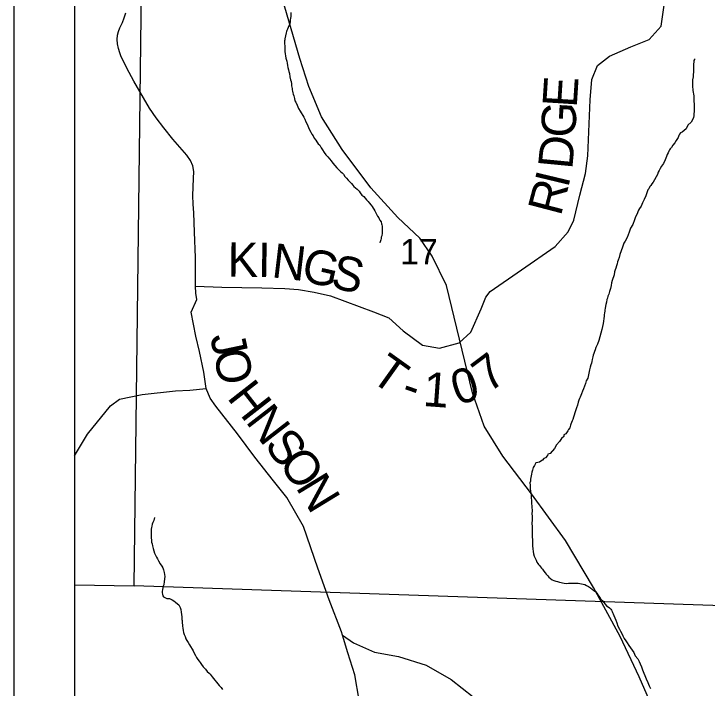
# Model space of a CAD drawing. Extents: x -14196 to 143, y -6096 to 28.
# Drawn here: x 58.003 to 59.148, y 19.711 to 20.825 of the extents above; entities that cross this region are included whole.
import ezdxf

# ---------------------------------------------------------------- set-up
doc = ezdxf.new("R2010")
doc.units = 0
for name, color, linetype in [('GM_X_Corporation', 7, 'Continuous'), ('GM_X_County_Road', 7, 'Continuous'), ('GM_X_County_Road_Text', 7, 'Continuous'), ('GM_X_Minor_River', 7, 'Continuous'), ('GM_X_Rail_Line', 7, 'Continuous'), ('GM_X_Section_Text', 7, 'Continuous'), ('GM_X_Township_Road', 7, 'Continuous'), ('GM_X_Township_Road_Text', 7, 'Continuous'), ('SH_Data', 7, 'Continuous')]:
    doc.layers.add(name, color=color, linetype=linetype)

msp = doc.modelspace()

# ---------------------------------------------------------------- linework, layer by layer
at = {"layer": 'GM_X_Corporation'}
for points in [[(64.9028, 18.7286), (64.9028, 23.6985), (58.1028, 23.6985), (58.1028, 18.8711)], [(62.1999, 18.7816), (62.2235, 19.866), (62.2323, 20.4208), (62.2487, 21.1358), (62.2751, 22.2884), (62.2815, 22.5484), (62.2824, 22.5866), (62.306, 23.4402), (61.9207, 23.4521), (60.7524, 23.485), (60.7179, 23.4857), (60.6994, 23.486), (60.6731, 23.4865), (60.4232, 23.4912), (60.4233, 23.5426), (60.4242, 23.5839), (60.4246, 23.6029), (60.4257, 23.6513), (60.4267, 23.6985), (58.1028, 23.6985), (58.1028, 18.8711)]]:
    msp.add_lwpolyline(points, dxfattribs=at)
for points in [[(58.1028, 20.874), (58.1028, 19.8822), (58.2013, 19.8806), (58.2134, 20.8668), (58.2133, 20.8703)], [(59.2185, 20.859), (59.2056, 19.8463), (58.2013, 19.8806), (58.2134, 20.8668)]]:
    msp.add_lwpolyline(points, close=True, dxfattribs=at)
at = {"layer": 'GM_X_County_Road'}
for points in [[(58.3029, 20.3753), (58.3027, 20.3824), (58.3027, 20.4227), (58.3014, 20.4645), (58.2999, 20.4966), (58.2989, 20.5108), (58.2985, 20.5254), (58.2995, 20.5532), (58.3002, 20.5649), (58.2983, 20.5742), (58.2946, 20.583), (58.2886, 20.5917), (58.2655, 20.6184), (58.2506, 20.6371), (58.2381, 20.6534), (58.2271, 20.6697), (58.2011, 20.714), (58.1931, 20.7284), (58.1882, 20.7376), (58.1842, 20.7458), (58.1803, 20.7541), (58.1776, 20.7611), (58.1755, 20.7679), (58.1739, 20.7758), (58.1734, 20.7828), (58.1738, 20.7898), (58.1755, 20.7959), (58.1781, 20.8022), (58.1825, 20.8111), (58.1851, 20.8185), (58.1878, 20.8268)], [(58.3206, 20.2064), (58.3165, 20.2333), (58.3092, 20.2673), (58.3033, 20.293), (58.2954, 20.3327), (58.3051, 20.3536), (58.3036, 20.3641), (58.3029, 20.3753)], [(58.5455, 19.7992), (58.5439, 19.8046), (58.5236, 19.8573), (58.5048, 19.9096), (58.481, 19.9782), (58.4536, 20.0262), (58.4316, 20.0537), (58.401, 20.0929), (58.3723, 20.1313), (58.3366, 20.1771), (58.3271, 20.1906), (58.3206, 20.2064)], [(58.5729, 19.6917), (58.5662, 19.7333), (58.5543, 19.7699), (58.5455, 19.7992)], [(58.5455, 19.7992), (58.5637, 19.7865), (58.5987, 19.771), (58.638, 19.764), (58.6835, 19.7496), (58.7251, 19.726), (58.7612, 19.6969)]]:
    msp.add_lwpolyline(points, dxfattribs=at)
at = {"layer": 'GM_X_Minor_River'}
for points in [[(58.4601, 20.8272), (58.4601, 20.8246), (58.4601, 20.8208), (58.4598, 20.8181), (58.4594, 20.8154), (58.4591, 20.8124), (58.4584, 20.809), (58.4569, 20.8055), (58.4558, 20.8025), (58.4547, 20.7998), (58.4539, 20.7979), (58.4532, 20.796), (58.4525, 20.7941), (58.4514, 20.7891), (58.4503, 20.7842), (58.4503, 20.7823), (58.45, 20.7804), (58.45, 20.7785), (58.45, 20.7751), (58.4501, 20.7728), (58.4501, 20.7701), (58.4501, 20.7682), (58.4501, 20.7659), (58.4506, 20.7633), (58.4518, 20.7519), (58.4538, 20.7473), (58.4542, 20.7436), (58.4546, 20.7398), (58.4554, 20.7367), (58.4562, 20.7329), (58.457, 20.7299), (58.4578, 20.7269), (58.4587, 20.7212), (58.4599, 20.7163), (58.461, 20.7136), (58.4611, 20.7098), (58.4615, 20.7064), (58.4619, 20.7041), (58.4623, 20.7022), (58.4627, 20.6996), (58.4631, 20.6977), (58.4635, 20.695), (58.4643, 20.6924), (58.4651, 20.6897), (58.4663, 20.6852), (58.4671, 20.6814), (58.4687, 20.6791), (58.4706, 20.6746), (58.473, 20.6689), (58.4757, 20.6644), (58.4815, 20.6545), (58.4834, 20.6511), (58.485, 20.647), (58.4873, 20.6428), (58.4893, 20.6375), (58.4912, 20.6337), (58.4932, 20.63), (58.4951, 20.6266), (58.4974, 20.6235), (58.499, 20.6201), (58.5013, 20.6167), (58.5032, 20.6137), (58.5056, 20.6103), (58.5079, 20.6081), (58.5102, 20.6039), (58.5125, 20.6005), (58.5152, 20.5964), (58.5183, 20.5926), (58.5214, 20.5888), (58.5241, 20.5858), (58.5268, 20.5824), (58.5299, 20.5787), (58.533, 20.5745), (58.5364, 20.5707), (58.5395, 20.5677), (58.5422, 20.5647), (58.5453, 20.5625), (58.5472, 20.5602), (58.5495, 20.5568), (58.5522, 20.5538), (58.5549, 20.5504), (58.558, 20.5474), (58.5603, 20.5448), (58.5626, 20.5421), (58.5645, 20.5399), (58.5668, 20.5376), (58.5699, 20.5354), (58.573, 20.5324)], [(59.1272, 20.7507), (59.1268, 20.7496), (59.1261, 20.7481), (59.1257, 20.7454), (59.1254, 20.7424), (59.1251, 20.7397), (59.1251, 20.737), (59.1251, 20.7351), (59.1251, 20.7332), (59.1252, 20.731), (59.1252, 20.7291), (59.1249, 20.7249), (59.1245, 20.7211), (59.1238, 20.7161), (59.1239, 20.7112), (59.1235, 20.707), (59.1236, 20.7036), (59.124, 20.7013), (59.124, 20.6994), (59.1248, 20.6952), (59.1252, 20.6929), (59.1257, 20.6895), (59.1261, 20.6846), (59.1261, 20.6804), (59.1262, 20.6766), (59.1262, 20.6736), (59.1263, 20.6641), (59.126, 20.6599), (59.1257, 20.6572), (59.1253, 20.6534), (59.1216, 20.6465), (59.116, 20.6412), (59.113, 20.6351), (59.1066, 20.6297), (59.1036, 20.6285), (59.1021, 20.6266), (59.101, 20.6243), (59.0999, 20.6212), (59.0969, 20.6163), (59.0943, 20.612), (59.0913, 20.6082), (59.0887, 20.6044), (59.0868, 20.6025), (59.0857, 20.6006), (59.0846, 20.5983), (59.0835, 20.5956), (59.082, 20.5929), (59.0805, 20.5895), (59.0783, 20.5841), (59.0757, 20.578), (59.0727, 20.5738), (59.0705, 20.5696), (59.0686, 20.5665), (59.0671, 20.5639), (59.0657, 20.5601), (59.0638, 20.5559), (59.0608, 20.5509), (59.0586, 20.5471), (59.0564, 20.5444), (59.0549, 20.5417), (59.0534, 20.5398), (59.0515, 20.5363), (59.05, 20.5344), (59.0482, 20.5298), (59.0463, 20.5249), (59.0437, 20.5188), (59.0412, 20.5131), (59.0386, 20.5077), (59.0363, 20.5035), (59.0345, 20.5008), (59.0319, 20.4936), (59.0297, 20.4901), (59.0278, 20.4852), (59.0249, 20.4772), (59.0215, 20.471), (59.0193, 20.4646), (59.0156, 20.4558), (59.0123, 20.4497), (59.0104, 20.4466), (59.0078, 20.4401), (59.006, 20.434), (59.0038, 20.4279), (59.0024, 20.4226), (59.0009, 20.4184), (58.9998, 20.4157), (58.9991, 20.4123), (58.998, 20.4088), (58.9969, 20.4054), (58.9958, 20.4024), (58.995, 20.3989), (58.994, 20.3944), (58.9929, 20.3909), (58.9921, 20.3883), (58.991, 20.3848), (58.9899, 20.381), (58.9892, 20.3768), (58.9881, 20.3715), (58.9863, 20.3665), (58.9852, 20.362), (58.9837, 20.3589), (58.983, 20.3558)], [(58.573, 20.5324), (58.5749, 20.5294), (58.5776, 20.526), (58.5807, 20.5233), (58.583, 20.5207), (58.5853, 20.5181), (58.588, 20.5154), (58.5899, 20.5132), (58.593, 20.509), (58.5945, 20.5071), (58.5988, 20.5), (58.6003, 20.4977), (58.6019, 20.4943), (58.6035, 20.4913), (58.6054, 20.4883), (58.6062, 20.4864), (58.607, 20.4845), (58.6093, 20.4815), (58.6101, 20.4784), (58.6105, 20.4765), (58.6109, 20.4746), (58.6113, 20.4708), (58.6113, 20.467), (58.611, 20.4648), (58.611, 20.4629), (58.6103, 20.4587), (58.6096, 20.4564), (58.6092, 20.4541), (58.6089, 20.4522), (58.6085, 20.4503), (58.6074, 20.4472), (58.607, 20.4472)], [(58.983, 20.3558), (58.9823, 20.3532), (58.9816, 20.349), (58.9805, 20.3452), (58.9798, 20.3425), (58.9794, 20.3383), (58.9791, 20.3364), (58.9787, 20.3345), (58.9784, 20.3307), (58.978, 20.3284), (58.9777, 20.3258), (58.9773, 20.322), (58.9766, 20.3178), (58.9759, 20.3136), (58.9748, 20.309), (58.9738, 20.3041), (58.9687, 20.2858), (58.9665, 20.2797), (58.9642, 20.2743), (58.9628, 20.2705), (58.9617, 20.2675), (58.9606, 20.2644), (58.9598, 20.2614), (58.9591, 20.2587), (58.9584, 20.2564), (58.958, 20.2541), (58.9573, 20.2511), (58.9566, 20.248), (58.9559, 20.2453), (58.9548, 20.2415), (58.9537, 20.237), (58.9522, 20.2316), (58.9508, 20.2236), (58.9482, 20.219), (58.9467, 20.2145), (58.9453, 20.2103), (58.9438, 20.2061), (58.9419, 20.2019), (58.9405, 20.1977), (58.939, 20.1946), (58.9379, 20.1923), (58.9371, 20.19), (58.936, 20.187), (58.9349, 20.1839), (58.9335, 20.179), (58.932, 20.1744), (58.9309, 20.171), (58.9294, 20.166), (58.928, 20.1622), (58.9269, 20.1588), (58.9258, 20.1553), (58.9247, 20.153), (58.9239, 20.1504), (58.9228, 20.1477), (58.9221, 20.1458), (58.921, 20.1416), (58.9188, 20.1389), (58.9176, 20.1366), (58.9143, 20.1313), (58.9113, 20.1301), (58.9109, 20.1274), (58.9072, 20.1236), (58.9038, 20.1186), (58.8989, 20.1136), (58.8956, 20.1075), (58.8885, 20.0991), (58.8847, 20.0979), (58.8839, 20.0956), (58.8806, 20.0921), (58.8783, 20.0906), (58.8761, 20.0883), (58.8734, 20.0864), (58.8708, 20.0848), (58.8681, 20.0844), (58.8651, 20.0836), (58.8636, 20.0813), (58.8625, 20.0794), (58.8603, 20.076), (58.8592, 20.0714), (58.8581, 20.0683), (58.8577, 20.0649), (58.8574, 20.0623), (58.8566, 20.0596), (58.8563, 20.0565), (58.856, 20.0535), (58.8552, 20.0508), (58.8557, 20.0466), (58.8557, 20.0413), (58.8562, 20.0364), (58.857, 20.0315), (58.8574, 20.028), (58.8574, 20.0254), (58.8579, 20.022), (58.8579, 20.0178), (58.8588, 20.0041), (58.8585, 19.9996), (58.8586, 19.9954), (58.8586, 19.9897), (58.8583, 19.9832), (58.8588, 19.9783), (58.8588, 19.9726)], [(58.2353, 19.9936), (58.2338, 19.9883), (58.2323, 19.9853), (58.2312, 19.9826), (58.2305, 19.9792), (58.2301, 19.9769), (58.2298, 19.9742), (58.2294, 19.9715), (58.2295, 19.9685), (58.2295, 19.9655), (58.2295, 19.9628), (58.2296, 19.9598), (58.23, 19.956), (58.2304, 19.9526), (58.2312, 19.9499), (58.232, 19.9465), (58.2328, 19.9423), (58.234, 19.9382), (58.2352, 19.9347), (58.2368, 19.931), (58.2383, 19.9279), (58.2399, 19.9253), (58.2418, 19.9215), (58.2442, 19.9166), (58.2472, 19.9132), (58.2488, 19.9102), (58.25, 19.9068), (58.2512, 19.9026), (58.2516, 19.8992), (58.252, 19.8958), (58.2513, 19.8878), (58.251, 19.8859), (58.2506, 19.884), (58.2503, 19.8821), (58.2495, 19.8798), (58.2488, 19.8779), (58.2481, 19.8737), (58.2477, 19.8714), (58.2478, 19.8687), (58.2482, 19.8665), (58.249, 19.8642), (58.2497, 19.8623), (58.252, 19.8612), (58.2555, 19.8593), (58.2574, 19.8594), (58.2597, 19.8594), (58.2623, 19.8586), (58.2642, 19.8575), (58.2669, 19.8557), (58.2696, 19.8534), (58.2731, 19.8508), (58.2754, 19.8489), (58.2765, 19.847), (58.2773, 19.8447), (58.2785, 19.8413), (58.2793, 19.8372), (58.2797, 19.833), (58.2801, 19.8292), (58.2802, 19.8269), (58.2802, 19.825), (58.2806, 19.8231), (58.2806, 19.8208), (58.2807, 19.8186), (58.2811, 19.8163), (58.2811, 19.8136), (58.2819, 19.8106), (58.2823, 19.8068), (58.2831, 19.8034), (58.2843, 19.8), (58.2859, 19.7966), (58.287, 19.7932), (58.2886, 19.7901), (58.2905, 19.7871), (58.2929, 19.783), (58.2987, 19.7731), (58.3006, 19.769), (58.3029, 19.7656), (58.3045, 19.7622), (58.3064, 19.7588), (58.3087, 19.7561), (58.3107, 19.7539), (58.3126, 19.7505), (58.3153, 19.7467), (58.3192, 19.743), (58.3222, 19.7388), (58.3253, 19.7362), (58.3272, 19.7343), (58.3303, 19.7302), (58.3326, 19.7275), (58.335, 19.7245), (58.3376, 19.7215), (58.3396, 19.7185), (58.3419, 19.7158), (58.345, 19.7125), (58.3473, 19.7094)], [(58.8588, 19.9726), (58.8589, 19.9665), (58.859, 19.9616), (58.8594, 19.9566), (58.8595, 19.9513), (58.8595, 19.9464), (58.86, 19.9418), (58.8604, 19.9372), (58.8608, 19.9335), (58.8624, 19.9293), (58.8632, 19.927), (58.8643, 19.9248), (58.8655, 19.9229), (58.8667, 19.9198), (58.8682, 19.9176), (58.8694, 19.9157), (58.8709, 19.9138), (58.8725, 19.9119), (58.8744, 19.9097), (58.8759, 19.9078), (58.8779, 19.9048), (58.8802, 19.9021), (58.8817, 19.8999), (58.8848, 19.8968), (58.8863, 19.895), (58.889, 19.8927), (58.8921, 19.8905), (58.8948, 19.8894), (58.8982, 19.8882), (58.9009, 19.8875), (58.9039, 19.8868), (58.907, 19.8861), (58.9092, 19.8857), (58.9119, 19.885), (58.9153, 19.8846), (58.9188, 19.8847), (58.9222, 19.8851), (58.9244, 19.8851), (58.9271, 19.8851), (58.9347, 19.8848), (58.9374, 19.8845), (58.9404, 19.8838), (58.9431, 19.8834), (58.9457, 19.8827), (58.9488, 19.8812), (58.9519, 19.8793), (58.9553, 19.8771), (58.958, 19.8748), (58.9607, 19.873), (58.9641, 19.8703), (58.9657, 19.8681), (58.9672, 19.8658), (58.9699, 19.862), (58.9719, 19.859), (58.9742, 19.8564), (58.9765, 19.8534), (58.9792, 19.8503), (58.9815, 19.8477), (58.9845, 19.8458), (58.9868, 19.8443), (58.9888, 19.8421), (58.9899, 19.8402), (58.9907, 19.8383), (58.9915, 19.8364), (58.9927, 19.8341), (58.9938, 19.8315), (58.9954, 19.8277), (58.997, 19.8239), (58.9989, 19.8194), (59.0005, 19.8141), (59.0032, 19.8088), (59.0048, 19.8054), (59.0067, 19.802), (59.0087, 19.7978), (59.011, 19.7937), (59.0133, 19.7899), (59.016, 19.7861), (59.0187, 19.782), (59.0214, 19.7778), (59.0241, 19.7744), (59.0265, 19.7703), (59.0292, 19.7646), (59.0331, 19.7597), (59.0354, 19.7556), (59.0373, 19.7514), (59.0393, 19.7465), (59.0413, 19.7416), (59.0471, 19.7268), (59.0499, 19.7207), (59.0522, 19.7151), (59.0545, 19.7109)]]:
    msp.add_lwpolyline(points, dxfattribs=at)
at = {"layer": 'GM_X_Rail_Line'}
msp.add_lwpolyline([(59.0619, 19.6698), (59.0358, 19.7301), (59.0043, 19.7967), (58.9599, 19.8777), (58.9137, 19.9553), (58.8575, 20.0323), (58.8104, 20.0944), (58.7796, 20.1441), (58.7604, 20.1993), (58.7174, 20.3768), (58.6937, 20.4252), (58.6734, 20.4548), (58.6371, 20.489), (58.5926, 20.5376), (58.5452, 20.6012), (58.5108, 20.6551), (58.49, 20.7054), (58.475, 20.7516), (58.439, 20.8767)], dxfattribs=at)
at = {"layer": 'GM_X_Township_Road'}
for points in [[(58.3029, 20.3753), (58.3462, 20.374), (58.4122, 20.3729), (58.4506, 20.3717), (58.4731, 20.3698), (58.4988, 20.3657), (58.526, 20.3595), (58.5966, 20.3328), (58.6223, 20.3232), (58.6457, 20.3014), (58.6778, 20.2779), (58.706, 20.2733), (58.7381, 20.2817), (58.7578, 20.2993), (58.7746, 20.3378), (58.7821, 20.3573), (58.7895, 20.3667), (58.841, 20.4022), (58.897, 20.4409), (58.9184, 20.4654), (58.9278, 20.4842), (58.9378, 20.5259), (58.9471, 20.5615), (58.9509, 20.5909), (58.9547, 20.6834), (58.9572, 20.7169), (58.9669, 20.7399), (58.9863, 20.7553), (59.022, 20.771), (59.0521, 20.7828), (59.072, 20.805), (59.0768, 20.8397)], [(58.3206, 20.2064), (58.3165, 20.2333), (58.3092, 20.2673), (58.3033, 20.293), (58.2954, 20.3327), (58.3051, 20.3536), (58.3036, 20.3641), (58.3029, 20.3753)], [(58.1028, 20.095), (58.1247, 20.131), (58.1626, 20.1776), (58.1775, 20.1887), (58.2145, 20.1964), (58.2695, 20.2028), (58.2934, 20.2038), (58.3206, 20.2064)]]:
    msp.add_lwpolyline(points, dxfattribs=at)
at = {"layer": 'SH_Data'}
for p, q in [((58.0028, 23.7985), (58.0028, 16.7985)), ((58.1028, 23.6985), (58.1028, 16.8985))]:
    msp.add_line(p, q, dxfattribs=at)

# ---------------------------------------------------------------- texts
at = {"layer": 'GM_X_County_Road_Text'}
for s, rotation, p in [('J', 281.965, (58.3267, 20.2926)), ('O', 280.847, (58.3322, 20.2668)), ('H', 307.9728, (58.3536, 20.1912)), ('N', 307.7296, (58.3843, 20.1518)), ('S', 307.7233, (58.4149, 20.1123)), ('O', 306.8276, (58.4383, 20.0821)), ('N', 301.4042, (58.4674, 20.0433))]:
    msp.add_text(s, height=0.0568, rotation=rotation, dxfattribs=at).set_placement(p)
at = {"layer": 'GM_X_Section_Text'}
msp.add_text('17', height=0.04186, rotation=0, dxfattribs=at).set_placement((58.6407, 20.4114))
at = {"layer": 'GM_X_Township_Road_Text'}
for s, rotation, p in [('E', 86.3934, (58.9324, 20.6695)), ('G', 86.9788, (58.9298, 20.6197)), ('D', 84.5485, (58.9249, 20.5673)), ('I', 76.5373, (58.918, 20.5361)), ('R', 75.3125, (58.9059, 20.4897)), ('K', 359.388, (58.3555, 20.3911)), ('I', 359.0242, (58.4054, 20.3906)), ('N', 353.2197, (58.4272, 20.3903)), ('G', 347.3289, (58.4754, 20.3846)), ('S', 347.1347, (58.5241, 20.3737)), ('T', 324.4494, (58.5893, 20.2213)), ('7', 36.8478, (58.7873, 20.1981)), ('1', 355.8024, (58.6774, 20.1777)), ('0', 17.9009, (58.7359, 20.178)), ('-', 341.165, (58.6399, 20.1884))]:
    msp.add_text(s, height=0.0568, rotation=rotation, dxfattribs=at).set_placement(p)

doc.saveas('drawing.dxf')
